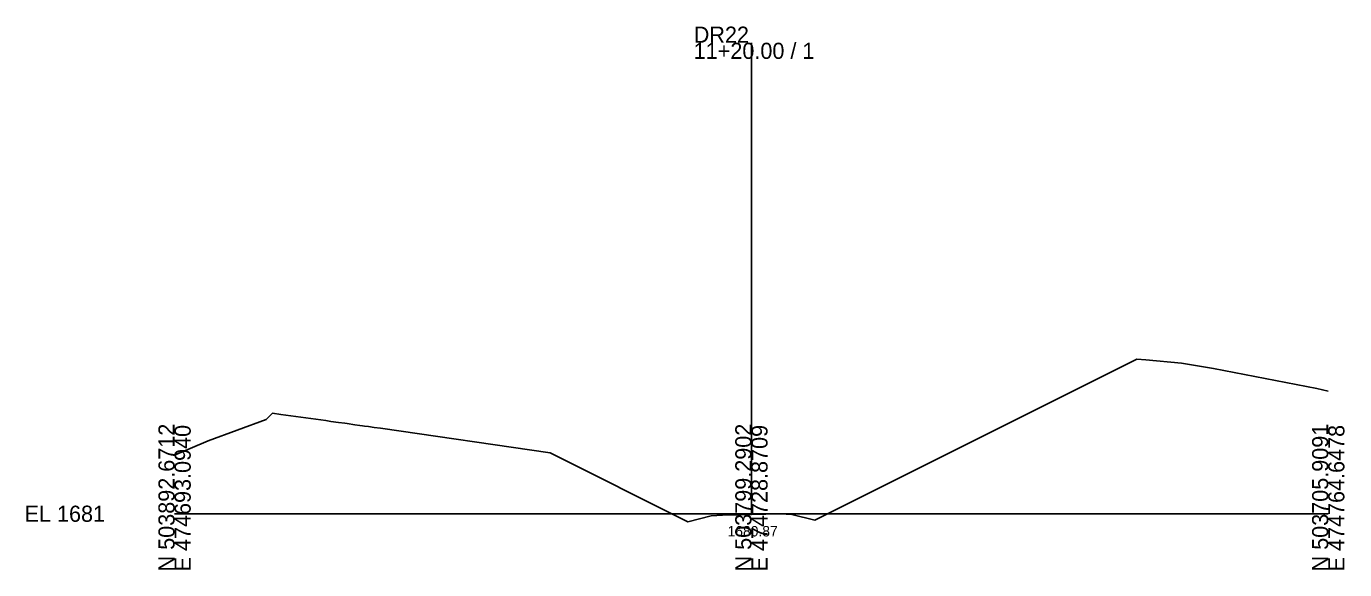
# Model space of a CAD drawing. Extents: x -26 to 1203, y -10 to 9633.
# Drawn here: x -25.7 to 202.8, y 2990.3 to 3084.5 of the extents above; entities that cross this region are included whole.
import ezdxf

# ---------------------------------------------------------------- set-up
doc = ezdxf.new("R2010")
doc.units = 0
for name, color, linetype in [('Exist Cross Section Cell', 7, 'Continuous'), ('Exist XS Center Line Elevation Label', 7, 'Continuous'), ('Exist XS Ground Line', 7, 'Continuous'), ('Scratch_Level_5', 7, 'Continuous')]:
    doc.layers.add(name, color=color, linetype=linetype)

msp = doc.modelspace()

# ---------------------------------------------------------------- linework, layer by layer
at = {"layer": 'Exist Cross Section Cell'}
for p, q in [((100, 3000), (100, 3081.67)), ((0, 3000), (100, 3000)), ((100, 3000), (200, 3000))]:
    msp.add_line(p, q, dxfattribs=at)
at = {"layer": 'Exist XS Ground Line'}
msp.add_lwpolyline([(0, 3010.18), (5.82, 3012.66), (15.88, 3016.35), (16.98, 3017.43), (18.43, 3017.23), (26.24, 3016.14), (27.11, 3016.02), (28.4, 3015.84), (29.5, 3015.68), (29.94, 3015.62), (31.26, 3015.44), (32.11, 3015.32), (32.55, 3015.26), (32.9, 3015.21), (33.63, 3015.11), (34.61, 3014.97), (35.7, 3014.82), (65.12, 3010.55), (89, 2998.61), (93, 2999.61), (93.98, 2999.69), (95, 2999.77), (100, 2999.87), (105, 2999.97), (106.02, 2999.93), (107, 2999.89), (111, 2998.89), (166.83, 3026.8), (168.35, 3026.67), (174.54, 3026.12), (180.1, 3025.19), (198.03, 3021.69), (200, 3021.24)], dxfattribs=at)
at = {"layer": 'Scratch_Level_5'}
msp.add_lwpolyline([(0, 3010.18), (5.82, 3012.66), (15.88, 3016.35), (16.98, 3017.43), (18.43, 3017.23), (26.24, 3016.14), (27.11, 3016.02), (28.4, 3015.84), (29.5, 3015.68), (29.94, 3015.62), (31.26, 3015.44), (32.11, 3015.32), (32.55, 3015.26), (32.9, 3015.21), (33.63, 3015.11), (34.61, 3014.97), (35.7, 3014.82), (65.12, 3010.55), (89, 2998.61), (93, 2999.61), (93.98, 2999.69), (95, 2999.77), (100, 2999.87), (105, 2999.97), (106.02, 2999.93), (107, 2999.89), (111, 2998.89), (166.83, 3026.8), (168.35, 3026.67), (174.54, 3026.12), (180.1, 3025.19), (198.03, 3021.69), (200, 3021.24)], dxfattribs=at)

# ---------------------------------------------------------------- texts
at = {"layer": 'Exist Cross Section Cell'}
for s, p in [('DR22', (90, 3081.67)), ('11+20.00 / 1', (90, 3078.87)), ('EL 1681', (-26, 2998.6))]:
    msp.add_text(s, height=2.8, dxfattribs=at).set_placement(p)
for s, p in [('N 503892.6712', (0, 2990)), ('E 474693.0940', (2.8, 2990)), ('N 503799.2902', (100, 2990)), ('E 474728.8709', (102.8, 2990)), ('N 503705.9091', (200, 2990)), ('E 474764.6478', (202.8, 2990))]:
    msp.add_text(s, height=2.8, rotation=90, dxfattribs=at).set_placement(p)
at = {"layer": 'Exist XS Center Line Elevation Label'}
msp.add_text('1680.87', height=1.8, dxfattribs=at).set_placement((95.86, 2996.07))

doc.saveas('drawing.dxf')
